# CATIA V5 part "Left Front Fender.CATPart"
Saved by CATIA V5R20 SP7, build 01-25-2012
Part number: Left Front Fender
Bounding box of the stored display mesh (mm): x -425.059 to 248.261, y -80 to 100, z 65 to 430
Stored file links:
  E:\#03 University\#02 영남 이공대\#01 2021\#02 여름 방학\#01 Documents\K-Move Page02 ASD01\Left Front Fender.CATPart

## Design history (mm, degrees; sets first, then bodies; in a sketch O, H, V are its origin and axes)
Set1 "Reference Data"
  Point1 "Center Point": (0, 0, 0)
  Plane1: type Offset, RefPlane zx-plane, Offset -80
  Plane2: type Offset, RefPlane Plane1, Offset 180
Body1 (main body)
Body2
  Sketch1 on zx-plane, origin (0, 0, 0), H (-1, 0, 0), V (0, 0, 1)
    arc A1 centre (0, 0) radius 430 from (425.0588, 65) to (0, 430) ccw
    line L1 (-219.3931, 380) -> (-248.2606, 430)
    line L2 (-248.2606, 430) -> (0, 430)
    point P2 (0, 430)
    point P4 (425.0588, 65)
    line L3 (-219.3931, 380) -> (0, 380)
    point P5 (-248.2606, 380)
    point P6 (0, 380)
    construction line L4 (-248.2606, 430) -> (-248.2606, 380)
    construction line L5 (0, 430) -> (0, 380)
    arc A2 centre (0, 0) radius 380 from (374.3995, 65) to (0, 380) ccw
    point P7 (0, 380)
    line L6 (425.0588, 65) -> (374.3995, 65)
    radius A1 = 430
    angle H L1 = 60
    distance H P4 = 65
    distance L2 L3 = 50
    coincidence: P2 A1, P2 V, P2 L2, P6 P7, O L1, P5 L3
    horizontal: L2 H, L6 H
    tangency: L2 A1, A2 L3
    perpendicularity: L4 L2, L4 L3, L5 L2, L5 L3
    concentricity: A2 A1
  Pad1: profile Sketch1, direction (0, 1, 0), up to Plane2, opposite side up to Plane1
  Fillet1: radius 50, on edge [face of Pad1 from Sketch1.L3 | face of Pad1 from Sketch1.L1]
  Fillet2: radius 30, on edge [end face of Pad1 | face of Pad1 from Sketch1.L2]
  Shell1: ExtOffset 0, Face (face of Pad1 from Sketch1.A2; face of Pad1 from Sketch1.L3; face of Fillet1; face of Pad1 from Sketch1.L1; face of Pad1 from Sketch1.L6; start face of Pad1), IntOffset 5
